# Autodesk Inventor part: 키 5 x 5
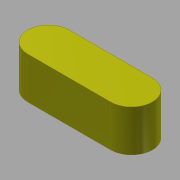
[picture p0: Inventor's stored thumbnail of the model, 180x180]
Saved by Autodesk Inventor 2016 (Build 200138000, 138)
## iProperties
Created: 2011-04
Part Number: 키 5 x 5
Document SubType Name: Modeling
Designer: pww
Density: 7.86 g/cm^3
Material: 강철, 연강
Appearance: 노란색
Author: pww
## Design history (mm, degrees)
sketch "스케치1"
  geometry: L1 (-5, -2.5)-(5, -2.5); L2 (5, 2.5)-(-5, 2.5); A1 r 2.5 centre (-5, 0) between (-5, 2.5) and (-5, -2.5); A2 r 2.5 centre (5, 0) between (5, -2.5) and (5, 2.5); 1 further point
  constraints: 4 end point, 4 point on circle, 2 centre point
extrude "돌출1" new body sketch "스케치1" distance "d0" = 5; taper "d1" = 0 deg
node "솔리드1"
